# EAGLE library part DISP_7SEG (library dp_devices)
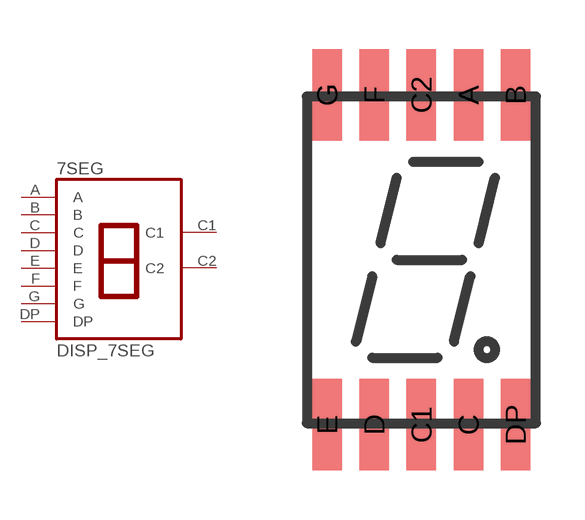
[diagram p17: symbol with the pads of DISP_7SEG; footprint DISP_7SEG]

Designator prefix 7SEG

## DISP_7SEG  [DISP_7SEG]
A  A
B  B
C  C
C1  C1
C2  C2
D  D
DP  DP
E  E
F  F
G  G

## Footprint DISP_7SEG (pad centres in mm)
smd 0.9 x 2.8: A 1.44,5.04; B 2.88,5.04; C 1.44,-5.04; C1 0,-5.04; C2 0,5.04; D -1.44,-5.04; DP 2.88,-5.04; E -2.88,-5.04; F -1.44,5.04; G -2.88,5.04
